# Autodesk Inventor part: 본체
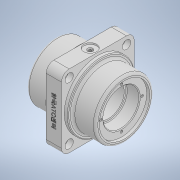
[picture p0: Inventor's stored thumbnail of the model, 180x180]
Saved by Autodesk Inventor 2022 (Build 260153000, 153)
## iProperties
Created: 2023-10
Part Number: 본체
Material: 일반
Document SubType Name: Modeling
Designer: PC-13
Density: 1 g/cm^3
Appearance: 기본값
Mass: 353.914 g
Surface Area: 541.824 cm^2
Volume: 353.914 cm^3
Author: PC-13
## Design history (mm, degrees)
sketch "스케치2"
  geometry: L1 (47.5, 47.5)-(-47.5, 47.5); L2 (-47.5, 47.5)-(-47.5, -47.5); L3 (-47.5, -47.5)-(47.5, -47.5); L4 (47.5, -47.5)-(47.5, 47.5); L5 (47.5, 47.5)-(-47.5, -47.5); L6 (-47.5, 47.5)-(47.5, -47.5); 1 further point
  constraints: 12 end point, 2 midpoint, 2 parallel, 1 horizontal, 1 perpendicular
  dimensions: "d2" = 95 distance between parallel lines of L2 L4; "d3" = 95 distance between parallel lines of L1 L3
extrude "돌출1" new body sketch "스케치2" stored distance "d4" = 20; taper "d5" = 0 deg
sketch "스케치3"
  geometry: C1 r 44 at (0, 0); 1 further point
  constraints: 1 centre point, 1 coincident
  dimensions: "d6" = 88 diameter of C1
extrude "돌출2" join sketch "스케치3" distance "d7" = 5; taper "d8" = 0 deg
sketch "스케치4"
  geometry: C1 r 38 at (0, 0); 1 further point
  constraints: 1 centre point, 1 coincident
  dimensions: "d9" = 76 diameter of C1
extrude "돌출3" join sketch "스케치4" distance "d10" = 30; taper "d11" = 0 deg
fillet "모깎기1" dims "d12" = 10
sketch "스케치6"
  geometry: C1 r 53 at (0, 0); A1 r 10 centre (-37.5, 37.5) between (-37.5, 47.5) and (-47.5, 37.5) reference; A2 r 10 centre (37.5, 37.5) between (47.5, 37.5) and (37.5, 47.5) reference; A3 r 10 centre (37.5, -37.5) between (37.5, -47.5) and (47.5, -37.5) reference; A4 r 10 centre (-37.5, -37.5) between (-47.5, -37.5) and (-37.5, -47.5) reference; 5 further points
  constraints: 5 coincident, 1 centre point
  dimensions: "d13" = 106 diameter of C1
hole "구멍1" sketch "스케치6" at (-37.5, 37.5), (37.5, 37.5), (37.5, -37.5), (-37.5, -37.5) diameter "d14" = 6.6; stored, may be unused: countersink angle "d18" = 90 deg, drill point angle "d20" = 118 deg; dims "d15" = 22, "d16" = 11, "d17" = 7, "d19" = 8
sketch "스케치7"
  geometry: C1 r 3.3 at (-37.5, -37.5) reference; C2 r 3.3 at (-37.5, 37.5) reference; C3 r 3.3 at (37.5, 37.5) reference; C4 r 3.3 at (37.5, -37.5) reference; C5 r 5.5 at (-37.5, -37.5); C6 r 5.5 at (-37.5, 37.5); C7 r 5.5 at (37.5, 37.5); C8 r 5.5 at (37.5, -37.5); 1 further point
  constraints: 4 centre point, 4 coincident
  dimensions: "d21" = 11 diameter of C5; "d22" = 11 diameter of C6; "d23" = 11 diameter of C7; "d24" = 11 diameter of C8
extrude "돌출4" cut sketch "스케치7" distance "d25" = 7; taper "d26" = 0 deg
chamfer "모따기1" distance "d27" = 1; stored, may be unused: second distance "d28" = 2, angle "d29" = 45 deg
fillet "모깎기2" dims "d30" = 3
fillet "모깎기3" dims "d31" = 3
sketch "스케치9"
  geometry: C1 r 33 at (0, 0); 1 further point
  constraints: 1 centre point, 1 coincident
  dimensions: "d32" = 66 diameter of C1
extrude "돌출5" cut sketch "스케치9" distance "d33" = 4; taper "d34" = 0 deg
sketch "스케치10"
  geometry: C1 r 23.5 at (0, 0); 1 further point
  constraints: 1 centre point, 1 coincident
  dimensions: "d35" = 47 diameter of C1
extrude "돌출6" cut sketch "스케치10" distance "d36" = 17; taper "d37" = 0 deg
sketch "스케치11"
  geometry: A1 r 27 centre (0, 0) between (0, 27) and (27, 0); 3 further points
  constraints: 4 point on circle, 2 horizontal alignment, 2 vertical alignment, 1 centre point, 1 coincident
  dimensions: "d38" = 54 diameter of A1
hole "구멍2" sketch "스케치11" at (0, 27), (27, 0), (0, -27), (-27, 0) diameter "d39" = 3.242; stored, may be unused: countersink angle "d43" = 90 deg, drill point angle "d45" = 118 deg; dims "d40" = 8, "d41" = 11, "d42" = 7, "d44" = 10
sketch "스케치12"
  geometry: L1 (0, 0)-(0, 75) reference; 2 further points
  constraints: 1 coincident, 1 other
  dimensions: "d46" = 10 distance from line of L1 point (10, 37.5)
extrude "돌출7" join sketch "스케치12" distance "d47" = 0.5; taper "d48" = 0 deg
sketch "스케치14"
  geometry: C1 r 8.5 at (10, -37.5); 1 further point
  constraints: 1 centre point, 1 coincident
  dimensions: "d49" = 17 diameter of C1
extrude "돌출8" cut sketch "스케치14" distance "d50" = 2; taper "d51" = 0 deg
sketch "스케치15"
  geometry: C1 r 8.5 at (0, 0) reference; 2 further points
  constraints: 1 coincident
hole "구멍3" sketch "스케치15" at (0, 0) diameter "d52" = 5.1881; stored, may be unused: countersink angle "d56" = 90 deg, drill point angle "d58" = 118 deg; dims "d53" = 14, "d54" = 7, "d55" = 2, "d57" = 30
sketch "스케치16"
  geometry: C1 r 20.5 at (0, 0); 1 further point
  constraints: 1 centre point, 1 coincident
  dimensions: "d59" = 41 diameter of C1
extrude "돌출9" cut sketch "스케치16" distance "d60" = 50; taper "d61" = 0 deg
chamfer "모따기2" distance "d62" = 1; stored, may be unused: second distance "d63" = 2, angle "d64" = 45 deg
fillet "모깎기4" dims "d65" = 1
node "솔리드1"
mirror "미러1"
node "작업 평면1"
feature "A9D066F2-1C7D-4E18-AEED-F7BC21143FA4" dims "d14" = 6.6, "d15" = 22, "d16" = 11, "d17" = 7, "d18" = 90 deg, "d19" = 8, "d20" = 118 deg
